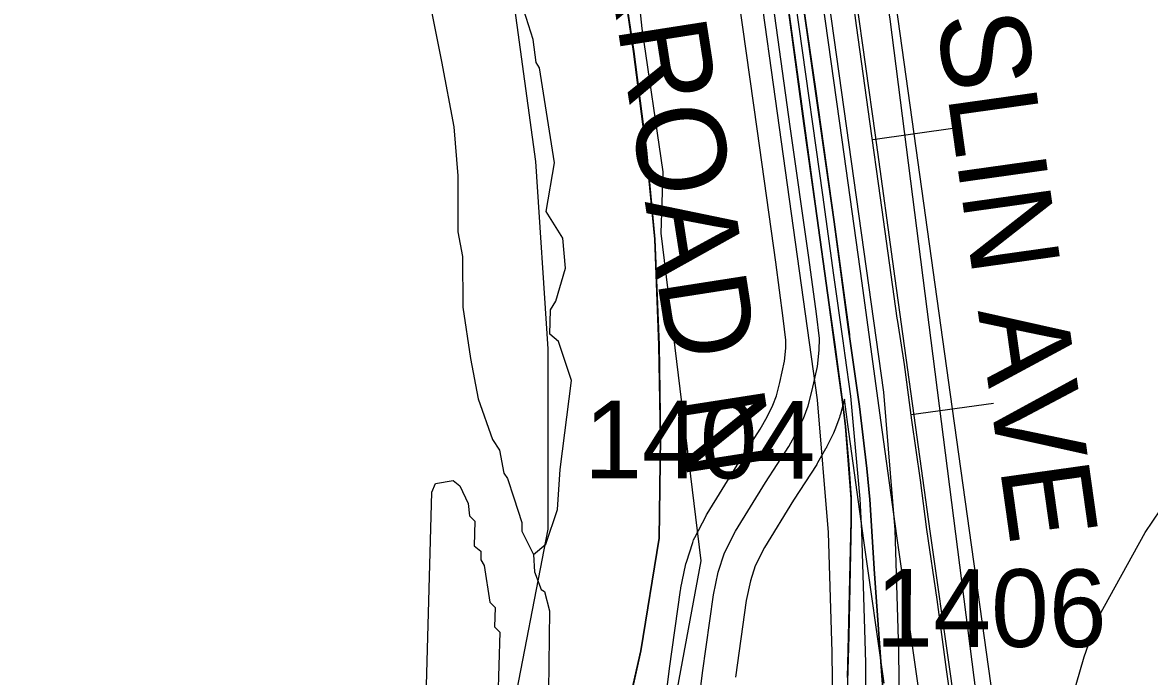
# Model space of a CAD drawing. Extents: x -132.8 to -73.3, y -60 to -26.
# Drawn here: x -123.901 to -122.885, y -47.025 to -46.436 of the extents above; entities that cross this region are included whole.
import ezdxf

# ---------------------------------------------------------------- set-up
doc = ezdxf.new("R2010")
doc.units = 0
for name, color, linetype in [('tdCoClipBndry', 7, 'Continuous'), ('tdCoCoBndry', 7, 'Continuous'), ('tdCoDivCarto', 7, 'Continuous'), ('tdCoHydroRiver', 7, 'Continuous'), ('tdCoInt', 7, 'Continuous'), ('tdCoIntCL', 7, 'Continuous'), ('tdCoIntRte', 7, 'Continuous'), ('tdCoPrimary', 7, 'Continuous'), ('tdCoRRCL', 7, 'Continuous'), ('tdCoSecRdNmbr', 7, 'Continuous'), ('tdCoSecRdTxt', 7, 'Continuous'), ('tdCoSecRteBand', 7, 'Continuous'), ('tdCoSecRteCL', 7, 'Continuous'), ('tdCoSectLine', 7, 'Continuous'), ('tdCoSectLinePart', 7, 'Continuous'), ('tdCoStBndry', 7, 'Continuous'), ('tdCoStBndryPart', 7, 'Continuous'), ('tdCoSurfGravel', 7, 'Continuous'), ('tdCoTwpBndryShd', 7, 'Continuous')]:
    doc.layers.add(name, color=color, linetype=linetype)

msp = doc.modelspace()

# ---------------------------------------------------------------- linework, layer by layer
at = {"layer": 'tdCoClipBndry'}
msp.add_lwpolyline([(-123.9235, -47.6606), (-123.8605, -47.607), (-123.7081, -47.4421), (-123.5655, -47.2993), (-123.5439, -47.2717), (-123.5256, -47.2444), (-123.4605, -47.0645), (-123.4272, -46.8921), (-123.4272, -46.7296), (-123.4382, -46.5607), (-123.4888, -46.1919), (-123.5022, -46.1438), (-123.564, -45.9554), (-123.6109, -45.845), (-123.7196, -45.7413), (-123.7728, -45.6723), (-123.9659, -45.4596), (-124.0151, -45.4132), (-124.1267, -45.3442)], dxfattribs=at)
at = {"layer": 'tdCoCoBndry'}
for p, q in [((-123.3497, -46.4616), (-123.3637, -46.3681)), ((-123.3383, -46.5507), (-123.3497, -46.4616)), ((-123.3307, -46.6309), (-123.3383, -46.5507)), ((-123.3269, -46.7263), (-123.3307, -46.6309)), ((-123.3256, -46.8097), (-123.3269, -46.7263)), ((-123.3268, -46.9001), (-123.3256, -46.8097)), ((-123.3432, -47.0018), (-123.3268, -46.9001)), ((-123.364, -47.0928), (-123.3432, -47.0018))]:
    msp.add_line(p, q, dxfattribs=at)
for points in [[(-123.364, -46.3681), (-123.3501, -46.4616), (-123.3387, -46.5507), (-123.3311, -46.6309), (-123.3273, -46.7263), (-123.326, -46.8097), (-123.3272, -46.9001), (-123.3436, -47.0018), (-123.3644, -47.0928), (-123.3893, -47.1613), (-123.4061, -47.2075), (-123.4268, -47.2644), (-123.4357, -47.29), (-123.4629, -47.3304), (-123.4905, -47.3656), (-123.5376, -47.415), (-123.5839, -47.4635), (-123.6347, -47.5099), (-123.6841, -47.5634), (-123.7911, -47.6793)], [(-123.7907, -47.6793), (-123.6837, -47.5634), (-123.6343, -47.5099), (-123.5835, -47.4635), (-123.5372, -47.415), (-123.4901, -47.3656), (-123.4625, -47.3304), (-123.4354, -47.29), (-123.4264, -47.2644), (-123.4057, -47.2075), (-123.389, -47.1613), (-123.364, -47.0928), (-123.3432, -47.0018), (-123.3268, -46.9001), (-123.3256, -46.8097), (-123.3269, -46.7263), (-123.3307, -46.6309), (-123.3383, -46.5507), (-123.3497, -46.4616), (-123.3637, -46.3681)]]:
    msp.add_lwpolyline(points, dxfattribs=at)
at = {"layer": 'tdCoDivCarto'}
for p, q in [((-123.2148, -46.3928), (-123.2004, -46.4976)), ((-123.186, -46.4954), (-123.1966, -46.4214)), ((-123.2004, -46.4976), (-123.1965, -46.5265)), ((-123.169, -46.6153), (-123.186, -46.4954)), ((-123.1965, -46.5265), (-123.1861, -46.601)), ((-123.1861, -46.601), (-123.1739, -46.6898)), ((-123.1552, -46.7186), (-123.169, -46.6153)), ((-123.1739, -46.6898), (-123.1697, -46.72)), ((-123.1739, -46.6898), (-123.1697, -46.72)), ((-123.1697, -46.72), (-123.1689, -46.7257)), ((-123.1689, -46.7257), (-123.1612, -46.782)), ((-123.1531, -46.7337), (-123.1552, -46.7186)), ((-123.1463, -46.7817), (-123.1531, -46.7337)), ((-123.1612, -46.782), (-123.1593, -46.7995)), ((-123.1396, -46.8375), (-123.1463, -46.7817)), ((-123.1593, -46.7995), (-123.1563, -46.8338)), ((-123.1563, -46.8338), (-123.1542, -46.8639)), ((-123.1369, -46.8653), (-123.1396, -46.8375)), ((-123.1542, -46.8639), (-123.1541, -46.8648)), ((-123.1541, -46.8648), (-123.1541, -46.8843)), ((-123.1327, -46.9324), (-123.1369, -46.8653)), ((-123.1541, -46.8843), (-123.1563, -46.9886)), ((-123.126, -47.024), (-123.1327, -46.9324)), ((-123.1563, -46.9886), (-123.1595, -47.1003)), ((-123.1244, -47.0471), (-123.126, -47.024))]:
    msp.add_line(p, q, dxfattribs=at)
for points in [[(-123.229, -46.2888), (-123.2182, -46.3679), (-123.2148, -46.3928), (-123.2004, -46.4976), (-123.1965, -46.5265), (-123.1861, -46.601), (-123.1739, -46.6898)], [(-123.229, -46.2888), (-123.2182, -46.3679), (-123.2148, -46.3928), (-123.2004, -46.4976), (-123.1965, -46.5265), (-123.1861, -46.601), (-123.1739, -46.6898)], [(-123.229, -46.2888), (-123.2182, -46.3679), (-123.2148, -46.3928), (-123.2004, -46.4976), (-123.1965, -46.5265), (-123.1861, -46.601), (-123.1739, -46.6898)], [(-123.1554, -46.7166), (-123.169, -46.6153), (-123.186, -46.4954), (-123.1966, -46.4214), (-123.2107, -46.3181), (-123.215, -46.2868)], [(-123.1554, -46.7166), (-123.169, -46.6153), (-123.186, -46.4954), (-123.1966, -46.4214), (-123.2107, -46.3181), (-123.215, -46.2868)], [(-123.1531, -46.7337), (-123.1552, -46.7186), (-123.169, -46.6153), (-123.186, -46.4954), (-123.1966, -46.4214), (-123.2107, -46.3181), (-123.2127, -46.3034)], [(-123.1739, -46.6898), (-123.1689, -46.7257), (-123.1612, -46.782), (-123.1593, -46.7995), (-123.1563, -46.8338), (-123.1541, -46.8648), (-123.1541, -46.8843), (-123.1563, -46.9886), (-123.1574, -47.0259)], [(-123.1739, -46.6898), (-123.1697, -46.72)], [(-123.126, -47.024), (-123.1327, -46.9324), (-123.1369, -46.8653), (-123.1396, -46.8375), (-123.1463, -46.7817), (-123.1552, -46.7186), (-123.1554, -46.7166)], [(-123.126, -47.024), (-123.1327, -46.9324), (-123.1369, -46.8653), (-123.1396, -46.8375), (-123.1463, -46.7817), (-123.1552, -46.7186), (-123.1554, -46.7166)], [(-123.1697, -46.72), (-123.1689, -46.7257), (-123.1612, -46.782), (-123.1593, -46.7995), (-123.1563, -46.8338), (-123.1542, -46.8639)], [(-123.1697, -46.72), (-123.1689, -46.7257), (-123.1612, -46.782), (-123.1593, -46.7995), (-123.1563, -46.8338), (-123.1542, -46.8639)], [(-123.126, -47.024), (-123.1327, -46.9324), (-123.1369, -46.8653), (-123.1396, -46.8375), (-123.1463, -46.7817), (-123.1531, -46.7337)], [(-123.1542, -46.8639), (-123.1541, -46.8648), (-123.1541, -46.8843), (-123.1563, -46.9886), (-123.1595, -47.1003), (-123.162, -47.1592)], [(-123.1542, -46.8639), (-123.1541, -46.8648), (-123.1541, -46.8843), (-123.1563, -46.9886), (-123.1595, -47.1003), (-123.162, -47.1592)], [(-123.1168, -47.1591), (-123.1209, -47.11), (-123.1244, -47.0471), (-123.126, -47.024)], [(-123.1168, -47.1591), (-123.1209, -47.11), (-123.1244, -47.0471), (-123.126, -47.024)], [(-123.1168, -47.1591), (-123.1209, -47.11), (-123.1244, -47.0471), (-123.126, -47.024)]]:
    msp.add_lwpolyline(points, dxfattribs=at)
at = {"layer": 'tdCoHydroRiver'}
for points in [[(-123.4404, -46.9148), (-123.4291, -46.9057), (-123.4188, -46.8744), (-123.4163, -46.8382), (-123.4062, -46.758), (-123.4179, -46.723), (-123.4256, -46.7164), (-123.425, -46.6944), (-123.4201, -46.6866), (-123.4114, -46.6569), (-123.4138, -46.63), (-123.4289, -46.6059), (-123.4214, -46.5619), (-123.4349, -46.4764), (-123.438, -46.4716), (-123.4406, -46.451), (-123.4638, -46.3778), (-123.4651, -46.3667), (-123.4698, -46.3634), (-123.4858, -46.2557), (-123.4904, -46.2493)], [(-123.6817, -47.7188), (-123.6049, -47.6279), (-123.5856, -47.6136), (-123.5353, -47.5638), (-123.4962, -47.5207), (-123.389, -47.3485), (-123.3624, -47.2972), (-123.3409, -47.2031), (-123.3351, -47.1638), (-123.3281, -47.1387), (-123.326, -47.1183), (-123.2891, -46.9205), (-123.3253, -46.6254), (-123.3236, -46.5702), (-123.3423, -46.4408), (-123.3512, -46.3575)], [(-123.5426, -46.3725), (-123.5232, -46.4708), (-123.5121, -46.5295), (-123.5086, -46.5738), (-123.5084, -46.6243), (-123.5042, -46.6465), (-123.5039, -46.6922), (-123.4972, -46.7382), (-123.4903, -46.7746), (-123.4771, -46.8113), (-123.471, -46.8209), (-123.4669, -46.8415), (-123.4638, -46.8463), (-123.458, -46.8639), (-123.4507, -46.8861), (-123.4509, -46.894), (-123.4404, -46.9148)], [(-123.5382, -47.0873), (-123.532, -46.8587), (-123.5287, -46.8509), (-123.5128, -46.8482), (-123.5066, -46.8531), (-123.4992, -46.8691), (-123.4979, -46.8801), (-123.4933, -46.885), (-123.4939, -46.9071), (-123.4877, -46.912), (-123.4879, -46.9198), (-123.4849, -46.9247), (-123.4795, -46.9579), (-123.4749, -46.9628), (-123.4753, -46.9801), (-123.4707, -46.985), (-123.4723, -47.0449)], [(-122.9426, -47.1839), (-122.9612, -47.1708), (-122.9671, -47.1564), (-122.9647, -47.1233), (-122.9545, -47.0968), (-122.9512, -47.0322), (-122.9442, -47.0071), (-122.9322, -46.9728), (-122.8891, -46.895), (-122.8545, -46.8439)], [(-123.4404, -46.9148), (-123.4393, -46.9306), (-123.4334, -46.9466), (-123.4303, -46.9482), (-123.426, -46.9657), (-123.427, -47.0619)]]:
    msp.add_lwpolyline(points, dxfattribs=at)
at = {"layer": 'tdCoInt'}
for points in [[(-123.1969, -47.6497), (-123.1559, -47.5791), (-123.1302, -47.5159), (-123.1065, -47.384), (-123.1111, -47.0016), (-123.1145, -46.8926), (-123.1247, -46.7686), (-123.214, -46.1299), (-123.2279, -46.0663), (-123.249, -45.9938), (-123.2667, -45.9421), (-123.2903, -45.8872), (-123.3305, -45.8019), (-123.376, -45.7271), (-123.5042, -45.5421), (-123.6902, -45.2828)], [(-123.297, -47.6901), (-123.2477, -47.6177), (-123.2099, -47.5527), (-123.1882, -47.4992), (-123.1666, -47.3789), (-123.1711, -47.0029), (-123.1744, -46.8951), (-123.1843, -46.7755), (-123.2731, -46.1404), (-123.2861, -46.0811), (-123.3062, -46.0119), (-123.3227, -45.9637), (-123.3692, -45.8602), (-123.3833, -45.8306), (-123.4264, -45.7597), (-123.5531, -45.5769), (-123.7405, -45.3156)]]:
    msp.add_lwpolyline(points, dxfattribs=at)
at = {"layer": 'tdCoIntCL'}
msp.add_lwpolyline([(-123.2223, -47.6337), (-123.1829, -47.5659), (-123.1592, -47.5076), (-123.1495, -47.4763), (-123.1443, -47.46), (-123.1395, -47.4375), (-123.1362, -47.4163), (-123.1371, -47.3184), (-123.1376, -47.2794), (-123.1391, -47.1609), (-123.1408, -47.0234), (-123.141, -47.0128), (-123.1411, -47.0023), (-123.1445, -46.8939), (-123.146, -46.8647), (-123.1545, -46.7721), (-123.1596, -46.7355), (-123.1614, -46.7223), (-123.1697, -46.6631), (-123.1797, -46.5908), (-123.2223, -46.2878)], dxfattribs=at)
at = {"layer": 'tdCoIntRte'}
for points in [[(-123.2151, -46.3928), (-123.2008, -46.4976), (-123.1969, -46.5265), (-123.1865, -46.601), (-123.1742, -46.6898), (-123.1693, -46.7257), (-123.1616, -46.782), (-123.1596, -46.7995), (-123.1567, -46.8338), (-123.1545, -46.8648), (-123.1545, -46.8843), (-123.1567, -46.9886), (-123.1578, -47.0259)], [(-123.2151, -46.3928), (-123.2008, -46.4976), (-123.1969, -46.5265), (-123.1865, -46.601), (-123.1742, -46.6898), (-123.1693, -46.7257), (-123.1616, -46.782), (-123.1596, -46.7995), (-123.1567, -46.8338), (-123.1545, -46.8648), (-123.1545, -46.8843), (-123.1567, -46.9886), (-123.1578, -47.0259)], [(-123.1247, -47.0471), (-123.1264, -47.024), (-123.1331, -46.9324), (-123.1373, -46.8653), (-123.14, -46.8375), (-123.1467, -46.7817), (-123.155, -46.7227), (-123.1556, -46.7186), (-123.1558, -46.7166), (-123.1694, -46.6153), (-123.1864, -46.4954), (-123.197, -46.4214)], [(-123.1247, -47.0471), (-123.1264, -47.024), (-123.1331, -46.9324), (-123.1373, -46.8653), (-123.14, -46.8375), (-123.1467, -46.7817), (-123.1556, -46.7186), (-123.1558, -46.7166), (-123.1694, -46.6153), (-123.1864, -46.4954), (-123.197, -46.4214)]]:
    msp.add_lwpolyline(points, dxfattribs=at)
at = {"layer": 'tdCoPrimary'}
msp.add_line((-123.1739, -46.6898), (-123.1697, -46.72), dxfattribs=at)
msp.add_line((-123.1739, -46.6898), (-123.1697, -46.72), dxfattribs=at)
for points in [[(-123.229, -46.2888), (-123.2182, -46.3679), (-123.2148, -46.3928), (-123.2004, -46.4976), (-123.1965, -46.5265), (-123.1861, -46.601), (-123.1739, -46.6898)], [(-123.229, -46.2888), (-123.2182, -46.3679), (-123.2148, -46.3928), (-123.2004, -46.4976), (-123.1965, -46.5265), (-123.1861, -46.601), (-123.1739, -46.6898)], [(-123.1531, -46.7337), (-123.1552, -46.7186), (-123.169, -46.6153), (-123.186, -46.4954), (-123.1966, -46.4214), (-123.2107, -46.3181), (-123.2127, -46.3034)], [(-123.1531, -46.7337), (-123.1552, -46.7186), (-123.169, -46.6153), (-123.186, -46.4954), (-123.1966, -46.4214), (-123.2107, -46.3181), (-123.2127, -46.3034)], [(-123.2148, -46.3928), (-123.2004, -46.4976), (-123.1965, -46.5265), (-123.1861, -46.601), (-123.1739, -46.6898), (-123.1697, -46.72), (-123.1689, -46.7257), (-123.1612, -46.782), (-123.1593, -46.7995), (-123.1563, -46.8338), (-123.1542, -46.8639), (-123.1541, -46.8648), (-123.1541, -46.8843), (-123.1563, -46.9886), (-123.1595, -47.1003)], [(-123.1244, -47.0471), (-123.126, -47.024), (-123.1327, -46.9324), (-123.1369, -46.8653), (-123.1396, -46.8375), (-123.1463, -46.7817), (-123.1531, -46.7337), (-123.1552, -46.7186), (-123.169, -46.6153), (-123.186, -46.4954), (-123.1966, -46.4214)], [(-123.1697, -46.72), (-123.1689, -46.7257), (-123.1612, -46.782), (-123.1593, -46.7995), (-123.1563, -46.8338), (-123.1542, -46.8639)], [(-123.1697, -46.72), (-123.1689, -46.7257), (-123.1612, -46.782), (-123.1593, -46.7995), (-123.1563, -46.8338), (-123.1542, -46.8639)], [(-123.126, -47.024), (-123.1327, -46.9324), (-123.1369, -46.8653), (-123.1396, -46.8375), (-123.1463, -46.7817), (-123.1531, -46.7337)], [(-123.126, -47.024), (-123.1327, -46.9324), (-123.1369, -46.8653), (-123.1396, -46.8375), (-123.1463, -46.7817), (-123.1531, -46.7337)], [(-123.1542, -46.8639), (-123.1541, -46.8648), (-123.1541, -46.8843), (-123.1563, -46.9886), (-123.1595, -47.1003), (-123.162, -47.1592)], [(-123.1542, -46.8639), (-123.1541, -46.8648), (-123.1541, -46.8843), (-123.1563, -46.9886), (-123.1595, -47.1003), (-123.162, -47.1592)], [(-123.1168, -47.1591), (-123.1209, -47.11), (-123.1244, -47.0471), (-123.126, -47.024)], [(-123.1168, -47.1591), (-123.1209, -47.11), (-123.1244, -47.0471), (-123.126, -47.024)]]:
    msp.add_lwpolyline(points, dxfattribs=at)
at = {"layer": 'tdCoRRCL'}
for p, q in [((-123.1346, -46.5411), (-123.0604, -46.5306)), ((-123.1, -46.7887), (-123.0257, -46.7786))]:
    msp.add_line(p, q, dxfattribs=at)
for points in [[(-124.5644, -39.5828), (-124.595, -40.997), (-124.6213, -41.6999), (-124.6444, -42.5874), (-124.6174, -42.7017), (-124.5989, -42.7795), (-124.5745, -42.87), (-124.3645, -43.4103), (-124.2879, -43.6206), (-124.2072, -43.8562), (-124.0007, -44.409), (-123.8311, -44.9246), (-123.7542, -45.1238), (-123.6724, -45.2553), (-123.3407, -45.7294), (-123.3115, -45.7601), (-123.2156, -45.9536), (-123.186, -46.0285), (-123.1192, -46.4325), (-123.0248, -47.1717), (-122.9661, -47.7049)], [(-123.1322, -46.288), (-123.0976, -46.5358), (-123.063, -46.7837), (-123.0286, -47.031), (-122.9938, -47.2788), (-123.0004, -47.5045), (-122.9954, -47.5431), (-122.9849, -47.6183), (-122.9836, -47.6271), (-122.9779, -47.666)], [(-123.1598, -46.3618), (-123.1496, -46.4383), (-123.1373, -46.5267), (-123.1279, -46.5935), (-123.1128, -46.7019), (-123.1124, -46.7049), (-123.1064, -46.7437), (-123.0996, -46.794), (-123.092, -46.848), (-123.0862, -46.8923), (-123.077, -46.9555), (-123.0684, -47.0187), (-123.0597, -47.0792), (-123.0516, -47.1361), (-123.0419, -47.2098), (-123.0327, -47.272), (-123.0324, -47.2746), (-123.0193, -47.3708), (-123.0106, -47.4356), (-123.0004, -47.5045), (-122.9954, -47.5431), (-122.9849, -47.6183), (-122.9836, -47.6271), (-122.9779, -47.666)]]:
    msp.add_lwpolyline(points, dxfattribs=at)
at = {"layer": 'tdCoSecRteBand'}
for points in [[(-123.3258, -47.0823), (-123.3178, -47.018), (-123.3178, -47.0178), (-123.3177, -47.0175), (-123.3079, -46.947), (-123.3077, -46.946), (-123.3075, -46.9451), (-123.3033, -46.9248), (-123.303, -46.9232), (-123.3025, -46.9217), (-123.2968, -46.9042), (-123.2961, -46.9018), (-123.2949, -46.8996), (-123.2848, -46.8801), (-123.2843, -46.8792), (-123.2838, -46.8783), (-123.2569, -46.8344), (-123.2567, -46.8341), (-123.2565, -46.8338), (-123.236, -46.802), (-123.2297, -46.7909), (-123.2246, -46.7805), (-123.2215, -46.772), (-123.2183, -46.7599), (-123.2141, -46.7408), (-123.2129, -46.7291), (-123.2128, -46.7218), (-123.2152, -46.702), (-123.2221, -46.6514), (-123.2386, -46.5334), (-123.2553, -46.4138)], [(-123.1499, -46.4131), (-123.1324, -46.5371), (-123.1324, -46.5372), (-123.1324, -46.5372), (-123.1146, -46.6662), (-123.0976, -46.7897), (-123.0976, -46.7897), (-123.0976, -46.7898), (-123.0833, -46.894), (-123.0648, -47.0224), (-123.0648, -47.0224), (-123.0648, -47.0225), (-123.0473, -47.1498)], [(-123.1242, -47.0308), (-123.1427, -46.9024), (-123.1427, -46.9023), (-123.1427, -46.9022), (-123.157, -46.7979), (-123.1602, -46.7749), (-123.1638, -46.7886), (-123.1642, -46.79), (-123.1647, -46.7914), (-123.1689, -46.8027), (-123.1694, -46.8042), (-123.1701, -46.8055), (-123.1763, -46.8181), (-123.1767, -46.819), (-123.1771, -46.8198), (-123.1843, -46.8323), (-123.1847, -46.833), (-123.1851, -46.8337), (-123.2059, -46.866), (-123.2321, -46.9087), (-123.2405, -46.925), (-123.2449, -46.9386), (-123.2486, -46.9563), (-123.2583, -47.0256)]]:
    msp.add_lwpolyline(points, dxfattribs=at)
at = {"layer": 'tdCoSecRteCL'}
for points in [[(-123.0597, -47.283), (-123.06, -47.2809), (-123.077, -47.1539), (-123.0945, -47.0266), (-123.113, -46.8981), (-123.1273, -46.7938), (-123.1443, -46.6703), (-123.1621, -46.5413), (-123.1796, -46.4173), (-123.1964, -46.2952), (-123.2016, -46.2583), (-123.2158, -46.1586), (-123.2309, -46.0767), (-123.2412, -46.039), (-123.2639, -45.9647), (-123.2842, -45.912), (-123.313, -45.8478), (-123.3394, -45.798), (-123.3719, -45.7435), (-123.3819, -45.7285)], [(-123.3304, -47.2693), (-123.3213, -47.2214), (-123.3085, -47.1573), (-123.3021, -47.1203), (-123.2962, -47.0868), (-123.288, -47.0217), (-123.2782, -46.9512), (-123.274, -46.9309), (-123.2683, -46.9134), (-123.2582, -46.8939), (-123.2313, -46.8501), (-123.2103, -46.8175), (-123.2032, -46.8049), (-123.197, -46.7923), (-123.1928, -46.781), (-123.1891, -46.7669), (-123.1845, -46.7455), (-123.183, -46.7309), (-123.1827, -46.7203), (-123.1854, -46.6981), (-123.1923, -46.6473), (-123.2089, -46.5292), (-123.2256, -46.4096)]]:
    msp.add_lwpolyline(points, dxfattribs=at)
at = {"layer": 'tdCoSectLine'}
msp.add_lwpolyline([(-123.3762, -46.2815), (-123.364, -46.3681), (-123.3501, -46.4616), (-123.3387, -46.5507), (-123.3311, -46.6309), (-123.3273, -46.7263), (-123.326, -46.8097), (-123.3272, -46.9001), (-123.3436, -47.0018), (-123.3644, -47.0928), (-123.3893, -47.1613), (-123.4061, -47.2075), (-123.4268, -47.2644)], dxfattribs=at)
at = {"layer": 'tdCoSectLinePart'}
msp.add_lwpolyline([(-123.3762, -46.2815), (-123.364, -46.3681), (-123.3501, -46.4616), (-123.3387, -46.5507), (-123.3311, -46.6309), (-123.3273, -46.7263), (-123.326, -46.8097), (-123.3272, -46.9001), (-123.3436, -47.0018), (-123.3644, -47.0928), (-123.3893, -47.1613), (-123.4061, -47.2075), (-123.4236, -47.2555)], dxfattribs=at)
at = {"layer": 'tdCoStBndry'}
msp.add_lwpolyline([(-123.364, -46.3681), (-123.3501, -46.4616), (-123.3387, -46.5507), (-123.3311, -46.6309), (-123.3273, -46.7263), (-123.326, -46.8097), (-123.3272, -46.9001), (-123.3436, -47.0018), (-123.3644, -47.0928), (-123.3893, -47.1613), (-123.4061, -47.2075), (-123.4268, -47.2644), (-123.4357, -47.29), (-123.4629, -47.3304), (-123.4905, -47.3656), (-123.5376, -47.415), (-123.5839, -47.4635), (-123.6347, -47.5099), (-123.6841, -47.5634), (-123.7911, -47.6793)], dxfattribs=at)
at = {"layer": 'tdCoStBndryPart'}
msp.add_lwpolyline([(-123.364, -46.3681), (-123.3501, -46.4616), (-123.3387, -46.5507), (-123.3311, -46.6309), (-123.3273, -46.7263), (-123.326, -46.8097), (-123.3272, -46.9001), (-123.3436, -47.0018), (-123.3644, -47.0928), (-123.3893, -47.1613), (-123.4061, -47.2075), (-123.4236, -47.2555)], dxfattribs=at)
at = {"layer": 'tdCoSurfGravel'}
for points in [[(-123.0597, -47.283), (-123.06, -47.2809), (-123.077, -47.1539), (-123.0945, -47.0266), (-123.113, -46.8981), (-123.1273, -46.7938), (-123.1443, -46.6703), (-123.1621, -46.5413), (-123.1796, -46.4173), (-123.1964, -46.2952), (-123.2016, -46.2583)], [(-123.3304, -47.2693), (-123.3213, -47.2214), (-123.3085, -47.1573), (-123.3021, -47.1203), (-123.2962, -47.0868), (-123.288, -47.0217), (-123.2782, -46.9512), (-123.274, -46.9309), (-123.2683, -46.9134), (-123.2582, -46.8939), (-123.2313, -46.8501), (-123.2103, -46.8175), (-123.2032, -46.8049), (-123.197, -46.7923), (-123.1928, -46.781), (-123.1891, -46.7669), (-123.1845, -46.7455), (-123.183, -46.7309), (-123.1827, -46.7203), (-123.1854, -46.6981), (-123.1923, -46.6473), (-123.2089, -46.5292), (-123.2256, -46.4096)]]:
    msp.add_lwpolyline(points, dxfattribs=at)
at = {"layer": 'tdCoTwpBndryShd'}
msp.add_lwpolyline([(-123.7911, -47.6793), (-123.6841, -47.5634), (-123.6347, -47.5099), (-123.5839, -47.4635), (-123.5376, -47.415), (-123.4905, -47.3656), (-123.4629, -47.3304), (-123.4357, -47.29), (-123.4268, -47.2644), (-123.4061, -47.2075), (-123.3893, -47.1613), (-123.3644, -47.0928), (-123.3436, -47.0018), (-123.3272, -46.9001), (-123.326, -46.8097), (-123.3273, -46.7263), (-123.3311, -46.6309), (-123.3387, -46.5507), (-123.3501, -46.4616), (-123.364, -46.3681)], dxfattribs=at)

# ---------------------------------------------------------------- texts
at = {"layer": 'tdCoSecRdNmbr'}
for s, rotation, p in [('1404', 359.9079, (-123.3946, -46.8462)), ('1406', 359.908, (-123.1322, -46.998))]:
    msp.add_text(s, height=0.07, rotation=rotation, dxfattribs=at).set_placement(p)
at = {"layer": 'tdCoSecRdTxt'}
for s, rotation, p in [('RIVERROAD N', 278.8749, (-123.4153, -46.1154)), ('JOSLIN AVE', 278, (-123.0963, -46.295))]:
    msp.add_text(s, height=0.08, rotation=rotation, dxfattribs=at).set_placement(p)

doc.saveas('drawing.dxf')
